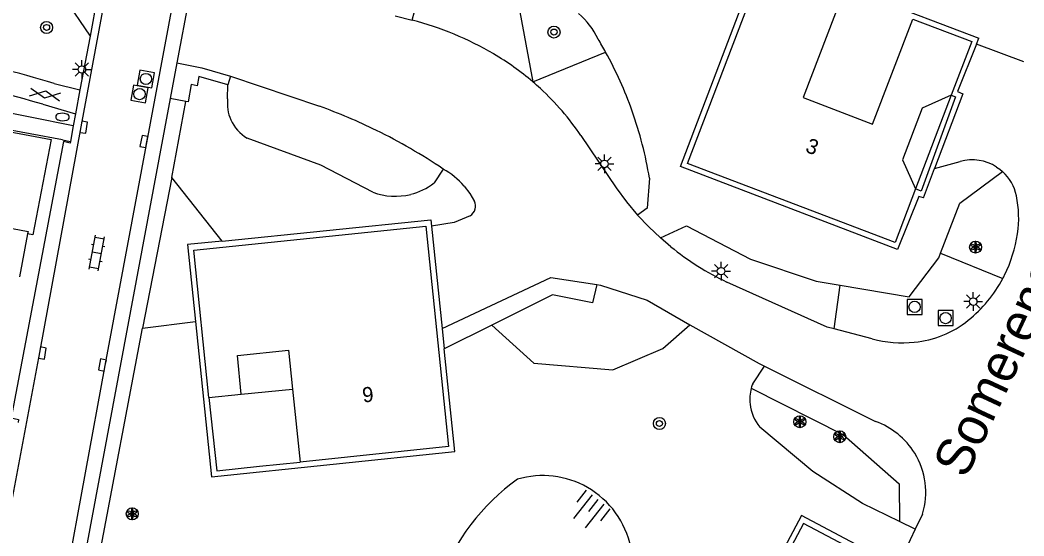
# Model space of a CAD drawing. Extents: x 124000 to 128010, y 398999 to 403000.
# Drawn here: x 126935.6 to 127002.2, y 399446.5 to 399480.8 of the extents above; entities that cross this region are included whole.
import ezdxf

# ---------------------------------------------------------------- set-up
doc = ezdxf.new("R2010")
doc.units = 0
for name, color, linetype in [('gg-afsc-erfafscheiding', 7, 'Continuous'), ('gg-afsc-hekwerk', 7, 'Continuous'), ('gg-afsc-muur', 7, 'Continuous'), ('gg-anno-huisnummerreeks BGT', 7, 'Continuous'), ('gg-anno-openbare ruimte label', 7, 'Continuous'), ('gg-bbg-bijgebouw', 7, 'Continuous'), ('gg-bbg-hoofdgebouw', 7, 'Continuous'), ('gg-bbg-luifel en loopbrug', 7, 'Continuous'), ('gg-knt-BGT kruinlijn', 7, 'Continuous'), ('gg-knt-verharding', 7, 'Continuous'), ('gt-grn-groengrens', 7, 'Continuous'), ('gt-grn-vlakafsluiter', 7, 'Continuous'), ('gt-grn-weggrens', 7, 'Continuous'), ('gt-symb-boom', 7, 'Continuous'), ('gt-symb-brandkraan', 7, 'Continuous'), ('gt-symb-gesloten verharding', 7, 'Continuous'), ('gt-symb-klinker verharding', 7, 'Continuous'), ('gt-symb-kolk', 7, 'Continuous'), ('gt-symb-lichtmast', 7, 'Continuous'), ('gt-symb-rioolschacht', 7, 'Continuous'), ('gt-symb-solitaire heester', 7, 'Continuous'), ('gt-symb-talud symbool', 7, 'Continuous')]:
    doc.layers.add(name, color=color, linetype=linetype)

# ---------------------------------------------------------------- blocks, each defined once
blk = doc.blocks.new('gt0-SH')
at = {"layer": 'gt-symb-solitaire heester'}
blk.add_circle((0, 0), 0.4, dxfattribs=at)
for centre, start, end in [((-0.346, 0.2), 270, 30), ((-0.346, -0.2), 330, 90), ((0, 0.4), 210, 330), ((0.346, 0.2), 150, 270), ((0.346, -0.2), 90, 210), ((0, -0.4), 30, 150)]:
    blk.add_arc(centre, 0.4, start, end, dxfattribs=at)
blk = doc.blocks.new('gt0-TALUD_1')
at = {"layer": 'gt-symb-talud symbool'}
for p, q in [((-1, -1), (-1, 0)), ((-0.5, -2), (-0.5, 0)), ((0, -1), (0, 0)), ((0.5, -2), (0.5, 0)), ((1, -1), (1, 0))]:
    blk.add_line(p, q, dxfattribs=at)
blk = doc.blocks.new('gt0-BOOM')
at = {"layer": 'gt-symb-boom'}
for radius in [0.4, 0.2]:
    blk.add_circle((0, 0), radius, dxfattribs=at)
blk = doc.blocks.new('gt0-LMAST')
at = {"layer": 'gt-symb-lichtmast'}
for p, q in [((-0.182, 0.173), (-0.447, 0.438)), ((-0.005, 0.246), (-0.005, 0.621)), ((0.172, 0.173), (0.437, 0.438)), ((-0.255, -0.004), (-0.63, -0.004)), ((-0.182, -0.181), (-0.447, -0.446)), ((-0.005, -0.254), (-0.005, -0.629)), ((0.437, -0.446), (0.172, -0.181)), ((0.245, -0.004), (0.62, -0.004))]:
    blk.add_line(p, q, dxfattribs=at)
blk.add_circle((-0.005, -0.004), 0.25, dxfattribs=at)
blk = doc.blocks.new('gt0-RS')
at = {"layer": 'gt-symb-rioolschacht'}
blk.add_lwpolyline([(-0.5, -0.5), (0.5, -0.5), (0.5, 0.5), (-0.5, 0.5)], close=True, dxfattribs=at)
blk.add_circle((0, 0), 0.375, dxfattribs=at)
blk = doc.blocks.new('gt0-GESVH1')
at = {"layer": 'gt-symb-gesloten verharding'}
for p, q in [((-0.992, -0.261), (0.008, 0.239)), ((0.008, -0.261), (-0.992, 0.239)), ((0.008, 0.239), (1.008, -0.261)), ((1.008, 0.239), (0.008, -0.261))]:
    blk.add_line(p, q, dxfattribs=at)
blk = doc.blocks.new('gt0-KOLK')
at = {"layer": 'gt-symb-kolk'}
blk.add_lwpolyline([(0, 0), (0.375, 0), (0.375, 0.4), (-0.375, 0.4), (-0.375, 0), (0, 0)], dxfattribs=at)
blk = doc.blocks.new('gt0-BR')
at = {"layer": 'gt-symb-brandkraan'}
for centre, radius, start, end in [((-0.244, 0), 0.206, 107.56694, 252.43307), ((0.599, -2.664), 3, 106.89205, 107.56694), ((0, -0.691), 0.938, 73.10799, 106.89205), ((-0.599, -2.664), 3, 72.43309, 73.10799), ((0.244, 0), 0.206, 287.56695, 72.43309), ((0.599, 2.664), 3, 252.43307, 253.10797), ((0, 0.691), 0.938, 253.10797, 286.89206), ((-0.599, 2.664), 3, 286.89206, 287.56695)]:
    blk.add_arc(centre, radius, start, end, dxfattribs=at)
blk = doc.blocks.new('gt0-KL1')
at = {"layer": 'gt-symb-klinker verharding'}
for p, q in [((-1.15, 0.3), (1.15, 0.3)), ((-1, -0.3), (-1, 0.3)), ((-0.5, 0.3), (-0.5, 0.45)), ((0, -0.3), (0, 0.3)), ((0.5, 0.3), (0.5, 0.45)), ((1, -0.3), (1, 0.3)), ((-1.15, -0.3), (1.15, -0.3)), ((-0.5, -0.45), (-0.5, -0.3)), ((0.5, -0.45), (0.5, -0.3))]:
    blk.add_line(p, q, dxfattribs=at)

msp = doc.modelspace()

# ---------------------------------------------------------------- linework, layer by layer
at = {"layer": 'gg-afsc-erfafscheiding'}
msp.add_line((126951.439, 399451.161), (126954.14, 399451.435), dxfattribs=at)
at = {"layer": 'gg-afsc-hekwerk'}
msp.add_line((126938.362, 399472.835), (126921.677, 399475.972), dxfattribs=at)
at = {"layer": 'gg-afsc-muur'}
msp.add_lwpolyline([(126948.086, 399455.73), (126948.621, 399450.862), (126951.439, 399451.161)], dxfattribs=at)
at = {"layer": 'gg-bbg-bijgebouw'}
msp.add_line((126936.056, 399466.589), (126935.517, 399463.733), dxfattribs=at)
msp.add_lwpolyline([(126930.162, 399467.876), (126936.088, 399466.758), (126936.056, 399466.589)], dxfattribs=at)
at = {"layer": 'gg-bbg-hoofdgebouw'}
for p, q in [((126948.086, 399455.73), (126950.243, 399455.943)), ((126953.635, 399456.278), (126954.14, 399451.435))]:
    msp.add_line(p, q, dxfattribs=at)
for points in [[(126994.993, 399469.577), (126993.64, 399466.032), (126979.86, 399471.271), (126984.948, 399484.593), (126990.193, 399482.595)], [(126990.193, 399482.595), (126987.553, 399475.653), (126992.15, 399473.89), (126994.821, 399480.856)], [(126994.821, 399480.856), (126998.734, 399479.361), (126997.372, 399475.809)], [(126997.372, 399475.809), (126995.439, 399474.944), (126994.133, 399471.52), (126994.993, 399469.577)], [(126948.086, 399455.73), (126947.081, 399465.515), (126962.496, 399467.11), (126964.007, 399452.462), (126954.14, 399451.435)], [(126950.243, 399455.943), (126949.979, 399458.509), (126953.364, 399458.875), (126953.635, 399456.278)], [(126989.769, 399430.138), (126993.895, 399427.927), (127000.547, 399440.498), (126987.568, 399447.366), (126980.926, 399434.814), (126985.064, 399432.619)]]:
    msp.add_lwpolyline(points, dxfattribs=at)
at = {"layer": 'gg-bbg-luifel en loopbrug'}
for p, q in [((126997.372, 399475.809), (126994.993, 399469.577)), ((126950.243, 399455.943), (126953.635, 399456.278))]:
    msp.add_line(p, q, dxfattribs=at)
msp.add_lwpolyline([(126930.162, 399467.876), (126931.325, 399474.045), (126937.62, 399472.859), (126936.402, 399466.524), (126936.056, 399466.589)], dxfattribs=at)
at = {"layer": 'gg-knt-BGT kruinlijn'}
for centre, radius, start, end in [((126970.259, 399444.581), 5.96, 60.20552, 106.37767), ((126977.004, 399438.522), 14.481, 125.58137, 159.92293), ((126970.266, 399444.587), 5.951, 11.47777, 60.23745)]:
    msp.add_arc(centre, radius, start, end, dxfattribs=at)
at = {"layer": 'gg-knt-verharding'}
for p, q in [((126937.172, 399484.223), (126940.197, 399479.723)), ((126947.12, 399484.099), (126945.968, 399477.944)), ((126960.463, 399481.085), (126961.589, 399480.795)), ((126940.197, 399479.723), (126939.532, 399476.157)), ((126999.039, 399479.203), (126999.196, 399479.597)), ((127002.198, 399478.031), (126999.039, 399479.203)), ((126945.968, 399477.944), (126945.528, 399475.596)), ((126937.826, 399476.578), (126939.532, 399476.157)), ((126949.532, 399477.059), (126949.339, 399476.483)), ((126949.532, 399477.059), (126955.427, 399475.074)), ((126939.532, 399476.157), (126939.234, 399474.566)), ((126945.528, 399475.596), (126933.171, 399409.609)), ((126937.065, 399475.206), (126939.234, 399474.566)), ((126946.559, 399475.396), (126945.528, 399475.596)), ((126939.234, 399474.566), (126939.088, 399473.781)), ((126939.088, 399473.781), (126938.894, 399472.735)), ((126996.255, 399470.93), (126997.968, 399471.408)), ((126995.539, 399468.982), (126996.255, 399470.93)), ((126962.86, 399467.116), (126963.571, 399460.314)), ((126978.752, 399465.745), (126978.066, 399466.329)), ((126963.571, 399460.314), (126970.795, 399463.697)), ((126970.795, 399463.697), (126973.849, 399463.231)), ((126966.868, 399460.533), (126963.713, 399458.96)), ((126963.571, 399460.314), (126963.713, 399458.96)), ((126992.124, 399459.622), (126989.604, 399460.282)), ((126984.974, 399457.804), (126992.338, 399454.136)), ((126995.467, 399447.987), (126994.985, 399446.982))]:
    msp.add_line(p, q, dxfattribs=at)
for points in [[(126944.485, 399500), (126939.587, 399473.706), (126936.837, 399458.712), (126928.724, 399415.495), (126925.981, 399400.56), (126911.09, 399321.653), (126906.668, 399319.738)], [(126918.239, 399314.105), (126915.165, 399319.891), (126916.306, 399325.001), (126924.705, 399369.522), (126927.489, 399384.524), (126938.592, 399443.591), (126941.213, 399457.849), (126949.077, 399500)], [(126995.539, 399468.982), (126995.228, 399469.068), (126993.801, 399465.546), (126979.4, 399471.08), (126984.728, 399485.115), (126999.196, 399479.597)], [(126961.589, 399480.795), (126961.731, 399481.374), (126961.162, 399481.513), (126961.207, 399481.896), (126960.639, 399482.021)], [(126999.039, 399479.203), (126997.783, 399476.056), (126998.142, 399475.897), (126996.255, 399470.93)], [(126945.968, 399477.944), (126947.619, 399477.616), (126949.532, 399477.059)], [(126949.339, 399476.483), (126947.43, 399477.036), (126947.312, 399476.419), (126946.923, 399476.507), (126946.708, 399475.367), (126946.559, 399475.396)], [(126997.372, 399475.809), (126997.655, 399475.706), (126995.368, 399469.434), (126994.993, 399469.577)], [(126938.894, 399472.735), (126938.872, 399472.618), (126938.443, 399472.729), (126934.971, 399454.37), (126935.456, 399454.269), (126935.42, 399454.077)], [(126972.792, 399473.12), (126975.13, 399469.653), (126975.814, 399468.727), (126976.553, 399467.844)], [(127000.388, 399471.033), (127000.589, 399470.892), (127000.777, 399470.734)], [(126965.033, 399469.774), (126965.409, 399469.284), (126965.722, 399468.752)], [(126978.066, 399466.329), (126977.288, 399467.065), (126976.553, 399467.844)], [(126948.977, 399466.116), (126962.817, 399467.53), (126962.86, 399467.116)], [(126965.431, 399467.785), (126964.371, 399467.347), (126962.86, 399467.116)], [(126948.977, 399466.116), (126946.672, 399465.881), (126947.198, 399460.775)], [(126973.849, 399463.231), (126973.551, 399462.022), (126970.89, 399462.538), (126966.868, 399460.533)], [(126973.849, 399463.231), (126974.093, 399463.194), (126977.189, 399462.197), (126980.02, 399460.544)], [(126989.604, 399460.282), (126989.143, 399460.403), (126982.473, 399463.393)], [(126947.198, 399460.775), (126948.262, 399450.459), (126964.426, 399452.139), (126963.713, 399458.96)], [(126980.02, 399460.544), (126984.621, 399457.98), (126984.974, 399457.804)], [(126993.554, 399444.646), (126987.426, 399447.885), (126980.386, 399434.621), (126994.041, 399427.424), (127001.069, 399440.653), (127000.726, 399440.855)], [(126994.985, 399446.982), (126994.309, 399445.573), (126993.554, 399444.646)]]:
    msp.add_lwpolyline(points, dxfattribs=at)
for centre, radius, start, end in [((126956.195, 399460.231), 21.26, 59.46804, 75.30126), ((126917.143, 399408.94), 70.729, 72.99695, 85.3517), ((126957.777, 399462.881), 18.173, 49.46594, 59.52144), ((126916.577, 399404.933), 73.198, 73.74598, 84.5022), ((126957.866, 399462.977), 18.043, 47.32281, 49.48016), ((126957.81, 399462.907), 18.132, 34.28066, 47.34378), ((126942.451, 399439.282), 38.072, 63.8818, 70.07235), ((126942.341, 399439.139), 38.249, 56.14669, 63.82819), ((126998.757, 399468.507), 3.007, 57.16246, 105.2207), ((126960.811, 399466.008), 5.657, 41.72805, 59.90069), ((126998.754, 399468.503), 3.012, 11.87759, 47.79584), ((126965.01, 399468.442), 0.776, 345.57956, 23.51395), ((126994.893, 399467.69), 6.958, 351.02239, 11.8884), ((126964.999, 399468.443), 0.787, 303.26512, 345.72964), ((126992.827, 399467.87), 9.027, 333.60161, 351.93515), ((126990.524, 399480.25), 18.681, 230.93711, 244.4699), ((126991.949, 399468.304), 10.007, 332.09595, 333.61454), ((126992.846, 399467.87), 9.011, 308.89817, 331.86687), ((126994.28, 399466.095), 6.729, 275.47198, 308.879), ((126994.155, 399467.371), 8.011, 255.31235, 275.49261), ((126990.683, 399449.428), 4.99, 31.31552, 70.62922), ((126990.683, 399449.42), 4.994, 343.32079, 31.39388)]:
    msp.add_arc(centre, radius, start, end, dxfattribs=at)
at = {"layer": 'gt-grn-groengrens'}
for p, q in [((126968.477, 399482.7), (126969.588, 399476.693)), ((126969.588, 399476.693), (126974.429, 399478.666)), ((126949.332, 399475.571), (126949.339, 399476.483)), ((126945.639, 399470.334), (126946.559, 399475.396)), ((126963.648, 399470.903), (126963.035, 399469.974)), ((126945.639, 399470.334), (126943.674, 399460.323)), ((126948.977, 399466.116), (126945.639, 399470.334)), ((126996.665, 399465.316), (127000.792, 399463.621)), ((126989.604, 399460.282), (126989.991, 399463.185)), ((126943.674, 399460.323), (126947.198, 399460.775)), ((126939.004, 399435.565), (126943.674, 399460.323)), ((126984.192, 399456.635), (126984.974, 399457.804)), ((126994.985, 399446.982), (126993.931, 399447.499))]:
    msp.add_line(p, q, dxfattribs=at)
for points in [[(126939.088, 399473.781), (126921.918, 399477.23), (126921.766, 399476.446)], [(126958.97, 399469.364), (126955.524, 399471.153), (126950.627, 399472.95)], [(126996.665, 399465.316), (126997.939, 399468.64), (127000.777, 399470.734)], [(126977.341, 399470.287), (126977.187, 399468.297), (126976.553, 399467.844)], [(126978.066, 399466.329), (126979.792, 399467.123), (126984.054, 399464.913), (126988.405, 399463.45), (126989.991, 399463.185)], [(126989.991, 399463.185), (126994.586, 399462.418), (126996.548, 399465.01), (126996.665, 399465.316)], [(126966.868, 399460.533), (126969.653, 399458.015), (126974.902, 399457.572), (126978.229, 399458.975), (126980.02, 399460.544)], [(126984.101, 399456.354), (126990.218, 399453.249), (126993.908, 399449.999), (126993.931, 399447.499)], [(126993.931, 399447.499), (126991.485, 399448.698), (126988.178, 399450.805), (126984.66, 399453.765)]]:
    msp.add_lwpolyline(points, dxfattribs=at)
for centre, radius, start, end in [((126969.299, 399477.339), 5.122, 25.39091, 49.47493), ((126951.374, 399465.901), 26.353, 28.97179, 31.15498), ((126951.717, 399466.105), 25.954, 19.4643, 28.94613), ((126952.029, 399475.271), 2.714, 173.64354, 203.89799), ((126951.476, 399465.991), 26.22, 9.42996, 19.52226), ((126952.024, 399475.272), 2.71, 203.97282, 238.96136), ((126960.45, 399473.316), 4.224, 284.24632, 307.72091), ((126960.457, 399473.298), 4.206, 249.29051, 284.21384), ((126986.881, 399455.609), 2.878, 159.11421, 164.99738), ((126986.907, 399455.603), 2.905, 165.02026, 186.14933), ((126986.9, 399455.604), 2.898, 186.17031, 219.37281)]:
    msp.add_arc(centre, radius, start, end, dxfattribs=at)
at = {"layer": 'gt-grn-vlakafsluiter'}
msp.add_line((126938.362, 399472.835), (126938.894, 399472.735), dxfattribs=at)
at = {"layer": 'gt-grn-weggrens'}
msp.add_line((126941.905, 399488.909), (126940.197, 399479.723), dxfattribs=at)

# ---------------------------------------------------------------- block references
at = {"layer": 'gt-symb-boom'}
for p in [(126937.317, 399480.304), (126971, 399480), (126978, 399454)]:
    msp.add_blockref('gt0-BOOM', p, dxfattribs=at)
at = {"layer": 'gt-symb-brandkraan', "rotation": 178.05074587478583}
msp.add_blockref('gt0-BR', (126938.368, 399474.358), dxfattribs=at)
at = {"layer": 'gt-symb-gesloten verharding', "rotation": -9.264523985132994}
msp.add_blockref('gt0-GESVH1', (126937.21, 399475.858), dxfattribs=at)
at = {"layer": 'gt-symb-klinker verharding', "rotation": 79.39794170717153}
msp.add_blockref('gt0-KL1', (126940.651, 399465.316), dxfattribs=at)
at = {"layer": 'gt-symb-kolk'}
for p, rotation in [((126939.587, 399473.706), -98.91603673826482), ((126943.976, 399472.697), 79.39794170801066), ((126936.837, 399458.712), -99.61302586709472), ((126941.213, 399457.849), 79.34163849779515)]:
    msp.add_blockref('gt0-KOLK', p, dxfattribs=dict(at, rotation=rotation))
at = {"layer": 'gt-symb-lichtmast'}
for p in [(126939.663, 399477.517), (126974.356, 399471.246), (126982.096, 399464.123), (126998.837, 399462.102)]:
    msp.add_blockref('gt0-LMAST', p, dxfattribs=at)
at = {"layer": 'gt-symb-rioolschacht', "rotation": -100.01793447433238}
for p in [(126943.906, 399476.882), (126943.485, 399475.882)]:
    msp.add_blockref('gt0-RS', p, dxfattribs=at)
at = {"layer": 'gt-symb-rioolschacht'}
for p in [(126994.939, 399461.747), (126997, 399461)]:
    msp.add_blockref('gt0-RS', p, dxfattribs=at)
at = {"layer": 'gt-symb-solitaire heester'}
for p in [(126998.987, 399465.717), (126987.321, 399454.12), (126989.97, 399453.124), (126943, 399448)]:
    msp.add_blockref('gt0-SH', p, dxfattribs=at)
at = {"layer": 'gt-symb-talud symbool', "xscale": 1.000312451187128, "yscale": 1.000312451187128, "rotation": -38.30199383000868}
msp.add_blockref('gt0-TALUD_1', (126973.939, 399448.943), dxfattribs=at)

# ---------------------------------------------------------------- texts
at = {"layer": 'gg-anno-huisnummerreeks BGT'}
for s, rotation, p in [('3', 339.2, (126987.63, 399472.061)), ('9', 5.9, (126958.325, 399455.39))]:
    msp.add_text(s, height=1, rotation=rotation, dxfattribs=at).set_placement(p)
at = {"layer": 'gg-anno-openbare ruimte label'}
msp.add_text('Somerenerf', height=2.5, rotation=65, dxfattribs=at).set_placement((126998.351, 399450.272))

doc.saveas('drawing.dxf')
